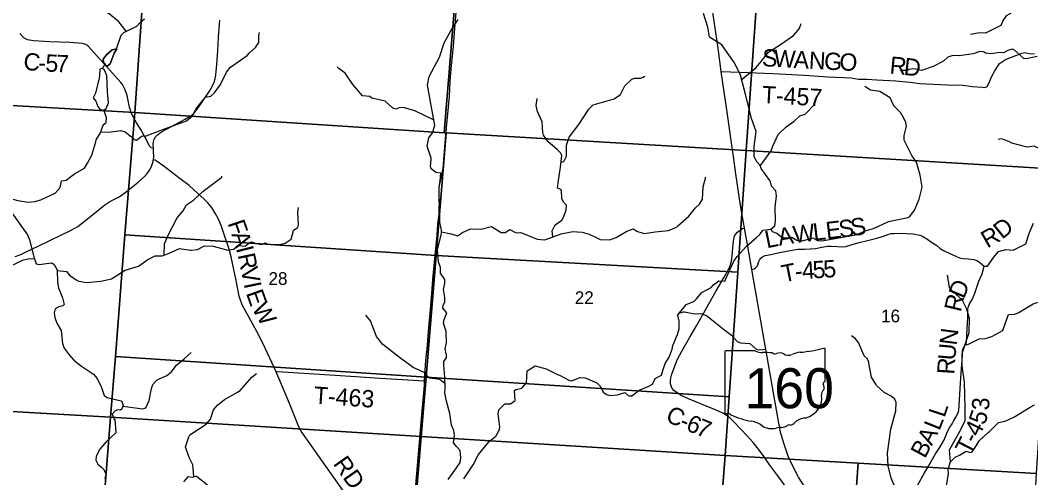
# Model space of a CAD drawing. Extents: x 1878108 to 2183446, y 146837 to 508383.
# Drawn here: x 2019382 to 2036927, y 325051 to 333002 of the extents above; entities that cross this region are included whole.
import ezdxf

# ---------------------------------------------------------------- set-up
doc = ezdxf.new("R2010")
doc.units = 0
for name, color, linetype in [('GM_X_County_Road', 7, 'Continuous'), ('GM_X_County_Road_Text', 7, 'Continuous'), ('GM_X_Minor_River', 7, 'Continuous'), ('GM_X_Section', 7, 'Continuous'), ('GM_X_Section_Text', 7, 'Continuous'), ('GM_X_State_Location', 7, 'Continuous'), ('GM_X_State_Route', 7, 'Continuous'), ('GM_X_State_Shield', 7, 'Continuous'), ('GM_X_Township_Road', 7, 'Continuous'), ('GM_X_Township_Road_Text', 7, 'Continuous')]:
    doc.layers.add(name, color=color, linetype=linetype)

msp = doc.modelspace()

# ---------------------------------------------------------------- linework, layer by layer
at = {"layer": 'GM_X_County_Road'}
for points in [[(2021694, 330779), (2021657, 330787), (2021633, 330810), (2021604, 330859), (2021557, 330956), (2021517, 331028), (2021476, 331101), (2021403, 331219), (2021342, 331322), (2021306, 331396), (2021281, 331490), (2021236, 331695), (2021204, 331794), (2021182, 331838), (2021158, 331884), (2021128, 331922), (2020833, 332251), (2020554, 332559), (2020521, 332581), (2020465, 332595), (2020246, 332612), (2019895, 332626), (2019611, 332642), (2019511, 332659), (2019444, 332693), (2019378, 332769)], [(2024994, 324816), (2024620, 325350), (2024257, 325861), (2024217, 325934), (2024056, 326341), (2023824, 326894), (2023598, 327379), (2023487, 327591), (2023235, 328056), (2023204, 328139), (2023185, 328209), (2023129, 328482), (2023067, 328783), (2023042, 328889), (2023008, 329025), (2022934, 329242), (2022869, 329436), (2022823, 329543), (2022770, 329640), (2022713, 329738), (2022640, 329828), (2022578, 329891), (2022397, 330057), (2022313, 330127), (2022157, 330244), (2021858, 330477), (2021757, 330549), (2021727, 330568), (2021697, 330574)], [(2032708, 324847), (2032533, 325086), (2032399, 325271), (2032285, 325431), (2032174, 325577), (2032105, 325666), (2032005, 325778), (2031886, 325902), (2031769, 326024), (2031704, 326091), (2031641, 326136), (2031578, 326173), (2031464, 326226), (2030982, 326424), (2030870, 326477), (2030789, 326525), (2030732, 326570), (2030703, 326603), (2030687, 326633), (2030674, 326681), (2030673, 326743), (2030679, 326785), (2030697, 326854), (2030734, 326960), (2030795, 327114), (2030867, 327250), (2031010, 327493), (2031123, 327693), (2031251, 327920), (2031339, 328076), (2031465, 328299), (2031602, 328535), (2031682, 328682), (2031714, 328754), (2031730, 328817), (2031744, 328906), (2031752, 329050), (2031763, 329161), (2031777, 329230), (2031795, 329270), (2031836, 329321), (2031869, 329350), (2031920, 329381), (2031956, 329391)]]:
    msp.add_lwpolyline(points, dxfattribs=at)
at = {"layer": 'GM_X_Minor_River'}
for points in [[(2037847, 334758), (2037838, 334558), (2037785, 334398), (2037647, 334207), (2037617, 334135), (2037617, 334051), (2037463, 333997), (2037366, 333946), (2037172, 333762), (2037056, 333721), (2036811, 333571), (2036785, 333549), (2036769, 333497), (2036763, 333471), (2036705, 333288), (2036561, 333110), (2036497, 333076), (2036446, 333003), (2036406, 332909), (2036222, 332817), (2036138, 332779), (2036036, 332780), (2035878, 332756)], [(2021222, 332809), (2021096, 332976), (2020928, 333114), (2020608, 333292), (2020441, 333362), (2020379, 333429), (2020312, 333560), (2020294, 333608)], [(2021056, 332503), (2021134, 332742), (2021182, 332790), (2021404, 332897), (2021464, 332963), (2021542, 333027)], [(2026450, 330845), (2026477, 330958), (2026542, 331044), (2026578, 331175), (2026536, 331429), (2026450, 331871), (2026481, 332023), (2026659, 332360), (2026744, 332609), (2026862, 332831), (2026984, 333012)], [(2031769, 328816), (2031827, 328899), (2031989, 329076), (2032164, 329224), (2032222, 329277), (2032276, 329355), (2032412, 329373), (2032482, 329427), (2032494, 329509), (2032489, 329752), (2032509, 329942), (2032503, 330036), (2032425, 330118), (2032409, 330196), (2032397, 330214), (2032243, 330428), (2032227, 330480), (2032175, 330534), (2032127, 330626), (2032125, 330806), (2032156, 331071), (2032080, 331295), (2031978, 331695), (2031889, 332046), (2031783, 332260), (2031653, 332440), (2031565, 332572), (2031351, 332706), (2031319, 332882), (2031243, 333120)], [(2031914, 331976), (2032161, 332180), (2032243, 332283), (2032373, 332447), (2032582, 332578), (2032808, 332734), (2032880, 332821), (2032913, 332865), (2032939, 332945)], [(2020782, 331060), (2020921, 331055), (2021126, 331086), (2021206, 331060), (2021378, 330922), (2021402, 330920), (2021446, 330950), (2021490, 330986), (2021568, 330991), (2021857, 331103), (2022267, 331254), (2022373, 331343), (2022430, 331457), (2022542, 331595), (2022600, 331665), (2022694, 331682), (2022754, 331738), (2022780, 331776), (2022855, 331876), (2022965, 332101), (2023035, 332187), (2023320, 332390), (2023358, 332432), (2023466, 332526), (2023524, 332614), (2023526, 332737), (2023534, 332791)], [(2021057, 332504), (2020977, 332487), (2020883, 332407), (2020823, 332325), (2020829, 332273), (2020859, 332243)], [(2020859, 332243), (2020829, 332273), (2020823, 332325), (2020883, 332407), (2020977, 332487), (2021057, 332504), (2021015, 332427), (2020941, 332243), (2020893, 332203), (2020875, 332211), (2020859, 332243)], [(2020859, 332243), (2020875, 332211), (2020893, 332203), (2020941, 332243), (2021015, 332427), (2021057, 332504)], [(2037038, 332372), (2036874, 332337), (2036814, 332329), (2036636, 332489), (2036602, 332497), (2036528, 332477), (2036454, 332435), (2036380, 332439), (2036244, 332416), (2036143, 332428), (2036117, 332446), (2036099, 332454), (2036043, 332456), (2035929, 332416), (2035681, 332383), (2035571, 332387), (2035485, 332359), (2035413, 332291), (2035232, 332196), (2035032, 332126), (2034896, 332155), (2034812, 332143), (2034788, 332127), (2034700, 332129)], [(2020834, 331438), (2020876, 331470), (2020912, 331564), (2020900, 331756), (2020888, 332043), (2020843, 332133), (2020809, 332165), (2020766, 332149), (2020756, 332042), (2020756, 332026), (2020690, 331736), (2020648, 331656), (2020692, 331596), (2020730, 331502), (2020762, 331456), (2020834, 331438)], [(2020766, 332149), (2020756, 332042), (2020756, 332026), (2020690, 331736), (2020648, 331656), (2020692, 331596), (2020730, 331502), (2020762, 331456), (2020834, 331438)], [(2020834, 331438), (2020876, 331470), (2020912, 331564), (2020900, 331756), (2020888, 332043), (2020843, 332133), (2020809, 332165), (2020766, 332149)], [(2020809, 332165), (2020859, 332243)], [(2026556, 331269), (2026234, 331426), (2026036, 331488), (2025953, 331480), (2025913, 331454), (2025851, 331476), (2025715, 331597), (2025489, 331649), (2025449, 331675), (2025323, 331687), (2025157, 331887), (2025021, 332083), (2024913, 332165), (2024887, 332191)], [(2028777, 330536), (2028818, 330548), (2028868, 330638), (2028866, 330828), (2028914, 330971), (2029079, 331191), (2029255, 331456), (2029331, 331532), (2029694, 331637), (2029802, 331709), (2029880, 331864), (2029998, 331978), (2030053, 331994), (2030155, 331994), (2030199, 332014), (2030225, 332027)], [(2032412, 329373), (2032434, 329329), (2032518, 329299), (2032590, 329245), (2032648, 329223), (2032780, 329232), (2032864, 329178), (2032964, 329168), (2033141, 329218), (2033221, 329172), (2033301, 329166), (2033695, 329237), (2033912, 329276), (2034036, 329338), (2034198, 329382), (2034442, 329501), (2034458, 329505), (2034791, 329574), (2034827, 329594), (2034905, 329700), (2034989, 329893), (2035042, 330099), (2035006, 330309), (2034940, 330535), (2034860, 330653), (2034730, 330917), (2034726, 330998), (2034767, 331162), (2034757, 331222), (2034699, 331348), (2034681, 331364), (2034671, 331392), (2034551, 331516), (2034485, 331654), (2034307, 331762), (2034145, 331788), (2034047, 331853)], [(2028626, 329237), (2028620, 329344), (2028668, 329444), (2028784, 329529), (2028812, 329581), (2028863, 329701), (2028867, 329791), (2028813, 329839), (2028783, 329903), (2028777, 330043), (2028769, 330059), (2028707, 330081), (2028723, 330177), (2028763, 330450), (2028784, 330654), (2028764, 330700), (2028724, 330738), (2028704, 330758), (2028550, 330886), (2028464, 331004), (2028456, 331052), (2028444, 331236), (2028362, 331416), (2028342, 331518), (2028356, 331643)], [(2032237, 330476), (2032418, 330735), (2032442, 330799), (2032538, 331018), (2032678, 331148), (2032817, 331248), (2032915, 331343), (2033007, 331371), (2033039, 331397), (2033149, 331515), (2033203, 331612)], [(2019049, 329960), (2019144, 329967), (2019252, 329895), (2019342, 329867), (2019522, 329841), (2019633, 329849), (2019739, 329880), (2019987, 329998), (2020077, 330093), (2020100, 330209), (2020182, 330225), (2020324, 330333), (2020500, 330432), (2020548, 330520), (2020627, 330656), (2020693, 330887), (2020703, 330921), (2020777, 331043), (2020817, 331169), (2020841, 331197), (2020872, 331224), (2020882, 331310), (2020834, 331438)], [(2037564, 330869), (2037516, 330867), (2037495, 330816), (2037375, 330760), (2037217, 330772), (2037097, 330764), (2036983, 330811), (2036865, 330797), (2036595, 330863), (2036545, 330897), (2036420, 330943), (2036360, 330930)], [(2026811, 325022), (2026955, 325223), (2027019, 325319), (2027031, 325398), (2027019, 325524), (2026953, 325602), (2026937, 325616), (2026907, 325658), (2026921, 325781), (2026909, 325875), (2026872, 325967), (2026842, 326168), (2026784, 326384), (2026756, 326527), (2026758, 326609), (2026752, 326799), (2026736, 327008), (2026736, 327074), (2026783, 327138), (2026781, 327193), (2026779, 327205), (2026759, 327299), (2026781, 327391), (2026779, 327594), (2026731, 327736), (2026743, 327804), (2026787, 327919), (2026719, 327997), (2026723, 328045), (2026753, 328109), (2026751, 328186), (2026732, 328320), (2026752, 328426), (2026752, 328498), (2026676, 328605), (2026676, 328619), (2026678, 328703), (2026644, 328805), (2026628, 329018), (2026694, 329291), (2026696, 329361), (2026665, 329485), (2026659, 329738), (2026655, 329935), (2026653, 330091), (2026673, 330209), (2026685, 330342), (2026599, 330358), (2026561, 330384), (2026519, 330422), (2026505, 330458), (2026515, 330590), (2026515, 330604), (2026448, 330815), (2026450, 330845)], [(2021881, 328921), (2021888, 329119), (2021955, 329277), (2022105, 329570), (2022211, 329692), (2022267, 329796), (2022388, 329875), (2022556, 330029), (2022883, 330276), (2022881, 330290)], [(2026694, 329322), (2026866, 329291), (2026976, 329253), (2027060, 329311), (2027200, 329377), (2027387, 329374), (2027565, 329416), (2027729, 329316), (2027801, 329314), (2027885, 329363), (2027979, 329313), (2028037, 329307), (2028075, 329311), (2028358, 329195), (2028482, 329184), (2028506, 329194), (2028774, 329290), (2028974, 329333), (2029139, 329317), (2029257, 329285), (2029359, 329237), (2029449, 329189), (2029621, 329188), (2029731, 329224), (2029911, 329338), (2030022, 329375), (2030098, 329329), (2030222, 329297), (2030406, 329327), (2030638, 329350), (2030776, 329408), (2030800, 329428), (2030987, 329599), (2031105, 329741), (2031177, 329803), (2031227, 329890), (2031238, 330106), (2031286, 330280)], [(2020022, 328653), (2020188, 328635), (2020238, 328573), (2020354, 328491), (2020402, 328465), (2020534, 328445), (2020784, 328466), (2020965, 328510), (2021203, 328657), (2021435, 328731), (2021596, 328844), (2021724, 328906), (2021848, 328908), (2021956, 328951), (2022146, 329033), (2022331, 329005), (2022347, 329005), (2022459, 329016), (2022583, 329080), (2022729, 329076), (2022989, 329009), (2023086, 329025), (2023138, 329063), (2023176, 329087), (2023288, 329073), (2023374, 329144), (2023404, 329152), (2023444, 329134), (2023564, 329106), (2023642, 329136), (2023668, 329112), (2023859, 329105), (2023883, 329105), (2023983, 329127), (2024085, 329199), (2024121, 329325), (2024129, 329351), (2024203, 329402), (2024215, 329448), (2024204, 329662), (2024214, 329748)], [(2019239, 329657), (2019391, 329434), (2019403, 329418), (2019511, 329270), (2019543, 329184), (2019621, 328889), (2019661, 328771), (2019719, 328757), (2019791, 328767), (2019929, 328785), (2019971, 328759), (2020001, 328705), (2020021, 328663), (2020031, 328445), (2020044, 328352), (2020114, 328180), (2020144, 328064), (2020122, 328038), (2020050, 328021), (2020038, 328017), (2019990, 327989), (2019972, 327915), (2019984, 327837), (2020018, 327738), (2020094, 327612), (2020116, 327386), (2020142, 327305), (2020234, 327187)], [(2019634, 328847), (2019543, 328856), (2019417, 328828), (2019263, 328751), (2019155, 328721), (2018948, 328656), (2018784, 328652), (2018614, 328618), (2018470, 328587), (2018271, 328467), (2018041, 328432), (2017603, 328400), (2017451, 328383), (2017242, 328389), (2017112, 328357), (2017090, 328351), (2016956, 328286), (2016810, 328162), (2016727, 328112), (2016475, 327895)], [(2030822, 327909), (2030913, 328024), (2030945, 328063), (2031077, 328113), (2031121, 328161), (2031214, 328273), (2031376, 328360), (2031420, 328404), (2031508, 328472), (2031616, 328470), (2031676, 328615), (2031769, 328817)], [(2035535, 325327), (2035515, 325537), (2035679, 325826), (2035790, 326043), (2035790, 326269), (2035777, 326710), (2035735, 326988), (2035733, 327210), (2035854, 327573), (2035862, 327821), (2035814, 327981), (2035738, 328141), (2035574, 328287), (2035514, 328357), (2035478, 328572)], [(2035480, 328558), (2035480, 328557)], [(2035782, 327357), (2035847, 327375), (2036030, 327465), (2036138, 327471), (2036228, 327501), (2036248, 327508), (2036440, 327612), (2036488, 327744), (2036541, 327891), (2036645, 327893), (2036709, 327917), (2036967, 328072), (2037112, 328122), (2037212, 328162)], [(2027085, 325033), (2027246, 325278), (2027340, 325456), (2027525, 325681), (2027637, 325777), (2027687, 325855), (2027695, 325872), (2027711, 325928), (2027681, 326162), (2027691, 326232), (2027796, 326334), (2027894, 326335), (2027972, 326393), (2027962, 326565), (2027992, 326587), (2028092, 326607), (2028171, 326702), (2028181, 326912), (2028323, 326996), (2028511, 326943), (2028709, 326847), (2028745, 326837), (2028917, 326739), (2028953, 326737), (2029046, 326769), (2029098, 326793), (2029190, 326786), (2029390, 326700), (2029460, 326632), (2029504, 326540), (2029562, 326498), (2029618, 326482), (2029750, 326494), (2029878, 326532), (2029938, 326479), (2029952, 326473), (2029998, 326475), (2030130, 326573), (2030293, 326645), (2030359, 326680), (2030407, 326776), (2030515, 326834), (2030537, 326914), (2030579, 327036), (2030646, 327149), (2030700, 327287), (2030710, 327351), (2030796, 327540), (2030820, 327638), (2030821, 327774), (2030799, 327876), (2030823, 327910), (2030893, 327932), (2030915, 327932), (2031091, 327901), (2031197, 327903), (2031297, 327869), (2031613, 327615), (2031733, 327531), (2031827, 327421), (2031885, 327397), (2032047, 327382), (2032159, 327288), (2032209, 327276), (2032328, 327288)], [(2026755, 326692), (2026665, 326757), (2026487, 326782), (2026393, 326882), (2026205, 326970), (2025969, 327142), (2025677, 327366), (2025567, 327504), (2025461, 327778), (2025380, 327875)], [(2034682, 324765), (2034550, 324933), (2034502, 325043), (2034450, 325259), (2034440, 325477), (2034495, 325898), (2034583, 326217), (2034592, 326359), (2034564, 326419), (2034500, 326467), (2034382, 326535), (2034248, 326655), (2034224, 326695), (2034160, 326797), (2034114, 327045), (2034114, 327059), (2034086, 327123), (2034036, 327171), (2033936, 327399), (2033882, 327467), (2033812, 327517), (2033812, 327516)], [(2021162, 326297), (2021509, 326250), (2021563, 326264), (2021621, 326392), (2021659, 326601), (2021683, 326673), (2021761, 326755), (2021930, 326826), (2022004, 326884), (2022094, 327008), (2022230, 327117), (2022347, 327227)], [(2020234, 327187), (2020314, 327097), (2020445, 326989), (2020653, 326853), (2020719, 326779), (2020787, 326634), (2020791, 326622), (2020841, 326482), (2020889, 326446), (2021135, 326388), (2021147, 326370), (2021167, 326312), (2021145, 326246), (2021117, 326228), (2021073, 326232), (2021023, 326210), (2020981, 326157), (2021007, 326079), (2021013, 326065), (2021025, 326071), (2021043, 325842), (2021043, 325832), (2020871, 325670), (2020766, 325551), (2020698, 325427), (2020692, 325360), (2020732, 325288), (2020794, 325234), (2020832, 325196), (2020868, 325118), (2020852, 325040)], [(2022396, 325071), (2022378, 325274), (2022313, 325405), (2022253, 325591), (2022309, 325765), (2022329, 325799), (2022608, 325982), (2022684, 326068), (2022736, 326230), (2022806, 326311), (2022928, 326409), (2023153, 326540), (2023203, 326570), (2023401, 326801), (2023482, 326865)], [(2035775, 326704), (2035776, 326705)], [(2035460, 324884), (2035498, 325119), (2035493, 325199), (2035535, 325327), (2035613, 325409), (2035689, 325446), (2035803, 325514), (2035875, 325492), (2035907, 325504), (2035959, 325580), (2036030, 325695), (2036190, 325841), (2036208, 325853), (2036368, 326014), (2036480, 326034), (2036631, 326104), (2036915, 326277), (2036993, 326319)], [(2022223, 324980), (2022303, 325076), (2022369, 325064), (2022431, 325079), (2022443, 325079), (2022631, 324927)]]:
    msp.add_lwpolyline(points, dxfattribs=at)
at = {"layer": 'GM_X_Section'}
for points in [[(2021742, 336707), (2021373, 331397), (2015959, 331706), (2015982, 331960), (2016318, 337016)], [(2027176, 336347), (2026745, 331046), (2021373, 331397), (2021742, 336707)], [(2032358, 336020), (2031987, 330736), (2026777, 331044), (2026745, 331046), (2027176, 336347)], [(2037721, 335715), (2037378, 330411), (2031987, 330736), (2032358, 336020)], [(2015959, 331706), (2021373, 331397), (2021200, 329271), (2021036, 327160), (2020952, 326107), (2015592, 326412), (2015609, 326604)], [(2021373, 331397), (2026745, 331046), (2026777, 331044), (2026602, 328916), (2021200, 329271)], [(2026777, 331044), (2031987, 330736), (2031841, 328623), (2026602, 328916)], [(2031987, 330736), (2037378, 330411), (2037233, 328304), (2037084, 326108), (2037018, 325126), (2033930, 325304), (2031621, 325441), (2031691, 326457), (2031841, 328623)], [(2021200, 329271), (2026602, 328916), (2026429, 326802), (2021036, 327160)], [(2026602, 328916), (2031841, 328623), (2031691, 326457), (2026429, 326802)], [(2026429, 326802), (2026345, 325770), (2020952, 326107), (2021036, 327160)], [(2031691, 326457), (2031621, 325441), (2026345, 325770), (2026429, 326802)], [(2020952, 326107), (2020858, 324918), (2020535, 320785), (2015233, 321110), (2015243, 321224), (2015592, 326412)], [(2020952, 326107), (2026345, 325770), (2026247, 324581), (2023639, 324740), (2020858, 324918)], [(2026345, 325770), (2031621, 325441), (2031529, 324243), (2030528, 324309), (2026522, 324560), (2026247, 324581)], [(2033930, 325304), (2033640, 321275), (2031322, 321425), (2031529, 324243), (2031621, 325441)], [(2036950, 323886), (2036627, 323893), (2036447, 321096), (2033640, 321275), (2033930, 325304), (2037018, 325126)]]:
    msp.add_lwpolyline(points, close=True, dxfattribs=at)
at = {"layer": 'GM_X_State_Route'}
for points in [[(2031736, 330830), (2031654, 331404), (2031554, 332111), (2031497, 332517), (2031435, 332946), (2031368, 333413)], [(2019296, 328895), (2019390, 328931), (2019473, 328971), (2019707, 329084), (2020087, 329267), (2020245, 329341), (2020319, 329382), (2020382, 329420), (2020608, 329595), (2020851, 329794), (2020922, 329843), (2020993, 329880), (2021076, 329921), (2021136, 329959), (2021206, 330009), (2021281, 330067), (2021343, 330120), (2021431, 330186), (2021537, 330289), (2021583, 330337), (2021625, 330395), (2021655, 330451), (2021680, 330515), (2021697, 330574), (2021702, 330636), (2021698, 330716), (2021694, 330779), (2021688, 330847), (2021695, 330891), (2021707, 330933), (2021730, 330973), (2021764, 331011), (2021795, 331035), (2021837, 331064), (2022243, 331283), (2022346, 331340), (2022394, 331379), (2022427, 331419), (2022472, 331480), (2022533, 331571), (2022667, 331769), (2022715, 331853), (2022747, 331926), (2022767, 331985), (2022776, 332048), (2022784, 332117), (2022795, 332225), (2022812, 332475), (2022827, 332710), (2022841, 332927), (2022850, 333005)], [(2026923, 332785), (2026928, 332865), (2026951, 333135), (2026953, 333154)], [(2026737, 330573), (2026738, 330580), (2026770, 331011), (2026832, 331676), (2026848, 331944), (2026865, 332156), (2026881, 332327), (2026906, 332553), (2026923, 332785)], [(2033022, 324866), (2032896, 325063), (2032790, 325264), (2032717, 325428), (2032649, 325619), (2032588, 325821), (2032550, 326003), (2032499, 326294), (2032130, 328405), (2032085, 328670), (2032008, 329103), (2031956, 329391), (2031888, 329780), (2031807, 330333), (2031764, 330633), (2031736, 330830)], [(2026658, 330105), (2026665, 330152), (2026694, 330292), (2026725, 330426), (2026737, 330573)], [(2026220, 324584), (2026358, 326217), (2026399, 326656), (2026402, 326734), (2026425, 327088), (2026451, 327351), (2026466, 327529), (2026510, 328040), (2026532, 328327), (2026546, 328498), (2026575, 328800), (2026620, 329268), (2026634, 329456), (2026653, 329634), (2026658, 329728), (2026662, 329833), (2026653, 329960), (2026653, 330067), (2026658, 330105)]]:
    msp.add_lwpolyline(points, dxfattribs=at)
at = {"layer": 'GM_X_State_Shield'}
for p, q in [((2031615, 327241), (2031615, 326184)), ((2032142, 327259), (2031632, 327259)), ((2033355, 326733), (2033355, 327285)), ((2033355, 326733), (2033355, 326733))]:
    msp.add_line(p, q, dxfattribs=at)
for centre, major_axis, start_param, end_param in [((2031635, 327243), (20.2, 0), 1.712693, 3.28349), ((2032263, 327382), (196, 0), 4.042523, 4.731795), ((2032328, 326666), (702, 0), 1.404758, 1.657858), ((2032487, 327249), (56.4, 0), 3.836095, 5.185415), ((2032570, 327127), (117, 0), 0.950623, 2.079405), ((2032971, 326937), (371, 0), 1.699011, 2.107814), ((2032735, 328700), (1845, 0), 4.814394, 5.042369), ((2033336, 327288), (19.4, 0), 6.141152, 7.989035), ((2032721, 327294), (141, 0), 4.081561, 5.145723), ((2033351, 326692), (30, 0), 1.883978, 3.671073), ((2033334, 326731), (20.7, 0), 5.05454, 6.418171), ((2033424, 326501), (131, 0), 2.387724, 3.262537), ((2033160, 326622), (180, 0), 5.934695, 6.695948), ((2032839, 326431), (462, 0), 5.101752, 6.440018), ((2031635, 326182), (20.3, 0), 3.00124, 4.508301), ((2031638, 326290), (155, 0), 4.665946, 4.897461), ((2031670, 326124), (56, 0), 0.519207, 1.627899), ((2032376, 327073), (1333, 0), 4.195997, 4.488961), ((2031979, 325710), (417, 0), 0.823519, 1.323587), ((2032713, 326082), (149, 0), 4.937069, 5.64225), ((2033033, 325888), (253, 0), 1.647645, 2.488434), ((2032430, 326118), (265, 0), 4.026481, 4.996735), ((2032583, 325753), (217, 0), 1.495662, 1.94098), ((2032602, 326039), (141, 0), 4.691044, 5.507374), ((2032730, 325937), (39.7, 0), 1.147584, 2.315152)]:
    msp.add_ellipse(centre, major_axis=major_axis, ratio=0.8, start_param=start_param, end_param=end_param, dxfattribs=at)
at = {"layer": 'GM_X_Township_Road'}
for points in [[(2031554, 332111), (2031878, 332099), (2032447, 332075), (2033000, 332047), (2033401, 332018), (2033808, 332002), (2033936, 331978), (2034088, 331979), (2034252, 331966), (2034582, 331947), (2034834, 331923), (2034996, 331900), (2035481, 331879), (2035753, 331871), (2035909, 331853), (2036091, 331839), (2036129, 331835), (2036168, 331852), (2036197, 331905), (2036247, 332018), (2036306, 332134), (2036382, 332248), (2036488, 332317), (2036770, 332427), (2036826, 332438), (2036897, 332425), (2036993, 332416)], [(2036115, 328727), (2036173, 328726), (2036284, 328885), (2036364, 328982), (2036496, 329016), (2036622, 329004), (2036838, 329115), (2036905, 329316), (2036971, 329478)], [(2032085, 328670), (2032123, 328681), (2032153, 328703), (2032181, 328735), (2032207, 328809), (2032225, 328846), (2032246, 328873), (2032277, 328894), (2032313, 328911), (2032414, 328932), (2032563, 328963), (2032751, 329002), (2032890, 329021), (2032998, 329025), (2033098, 329031), (2033187, 329038), (2033297, 329059), (2033398, 329075), (2033461, 329077), (2033570, 329069), (2033652, 329062), (2033715, 329068), (2033841, 329108), (2033945, 329142), (2034092, 329175), (2034253, 329217), (2034368, 329252), (2034460, 329285), (2034502, 329293), (2034556, 329298), (2034658, 329304), (2034878, 329289), (2034999, 329269), (2035048, 329247), (2035120, 329204), (2035203, 329145), (2035294, 329085), (2035354, 329035), (2035413, 328999), (2035523, 328947), (2035638, 328894), (2035688, 328875), (2035755, 328863), (2035841, 328854), (2035940, 328845), (2035992, 328829), (2036037, 328799), (2036115, 328727)], [(2035132, 325225), (2035156, 325264), (2035227, 325384), (2035275, 325465), (2035354, 325590), (2035418, 325697), (2035449, 325780), (2035480, 325855), (2035524, 325931), (2035560, 325991), (2035583, 326035), (2035624, 326107), (2035658, 326168), (2035676, 326223), (2035682, 326305), (2035696, 326507), (2035714, 326790), (2035722, 326949), (2035736, 327086), (2035740, 327195), (2035741, 327254), (2035749, 327286), (2035770, 327326), (2035799, 327371), (2035808, 327416), (2035815, 327532), (2035822, 327640), (2035835, 327828), (2035836, 327980), (2035844, 328026), (2035856, 328065), (2035910, 328151), (2035950, 328241), (2035999, 328400), (2036025, 328465), (2036081, 328595), (2036100, 328656), (2036102, 328666), (2036115, 328727)], [(2023824, 326894), (2023851, 326897), (2024032, 326889), (2024850, 326833), (2025289, 326803), (2025539, 326789), (2026402, 326734)], [(2034654, 324353), (2034722, 324482), (2034854, 324727), (2034958, 324915), (2035079, 325140), (2035132, 325225)]]:
    msp.add_lwpolyline(points, dxfattribs=at)

# ---------------------------------------------------------------- texts
at = {"layer": 'GM_X_County_Road_Text'}
for s, rotation, p in [('C', 354.1865, (2019427, 332144)), ('5', 357.4387, (2019814, 332111)), ('7', 357.5886, (2019999, 332103)), ('-', 357.0158, (2019688, 332117)), ('F', 288.7896, (2022980, 329475)), ('A', 288.2748, (2023045, 329284)), ('I', 284.4301, (2023126, 329039)), ('R', 282.0272, (2023156, 328923)), ('V', 281.735, (2023207, 328682)), ('I', 281.8287, (2023261, 328423)), ('E', 289.6214, (2023298, 328260)), ('W', 299.418, (2023397, 327997)), ('C', 333.1609, (2030566, 326052)), ('-', 337.6923, (2030810, 325930)), ('6', 337.7491, (2030924, 325883)), ('7', 337.3317, (2031095, 325814)), ('RD', 305.1937, (2024804, 325294))]:
    msp.add_text(s, height=300, rotation=rotation, dxfattribs=at).set_placement(p)
at = {"layer": 'GM_X_Section_Text'}
for s, p in [('28', (2023693, 328403)), ('22', (2029010, 328071)), ('16', (2034328, 327752))]:
    msp.add_text(s, height=221, rotation=0, dxfattribs=at).set_placement(p)
at = {"layer": 'GM_X_State_Location'}
msp.add_text('160', height=1, rotation=0, dxfattribs=at).set_placement((2032112, 326570))
for s in ['s', 'r']:
    msp.add_text(s, height=1, dxfattribs=at).set_placement((2032465, 326643))
at = {"layer": 'GM_X_State_Shield'}
msp.add_text('160', height=696.1, dxfattribs=at).set_placement((2031956, 326259))
at = {"layer": 'GM_X_Township_Road_Text'}
for s, rotation, p in [('S', 356.929, (2032255, 332204)), ('W', 356.9276, (2032457, 332193)), ('A', 356.9277, (2032804, 332174)), ('N', 356.9277, (2033068, 332160)), ('G', 356.9338, (2033332, 332146)), ('O', 357.5587, (2033599, 332132)), ('R', 354.6335, (2034468, 332076)), ('D', 353.6377, (2034712, 332053)), ('T-457', 356.9129, (2032252, 331562)), ('E', 6.7135, (2033385, 329195)), ('S', 6.8068, (2033608, 329221)), ('S', 9.0968, (2033822, 329247)), ('D', 39.2532, (2036430, 329185)), ('L', 11.5159, (2032343, 329038)), ('A', 9.6629, (2032561, 329082)), ('W', 7.0783, (2032817, 329126)), ('L', 6.7136, (2033162, 329169)), ('R', 29.7696, (2036172, 329033)), ('4', 3.9269, (2032965, 328501)), ('5', 3.713, (2033149, 328514)), ('5', 3.6922, (2033334, 328526)), ('T', 11.4763, (2032633, 328445)), ('-', 6.2497, (2032846, 328488)), ('D', 67.24, (2035764, 328148)), ('R', 76.5686, (2035711, 327920)), ('N', 82.772, (2035637, 327343)), ('U', 84.8313, (2035614, 327083)), ('R', 86.3131, (2035598, 326840)), ('T-463', 356.0726, (2024473, 326340)), ('3', 87.4669, (2036201, 326218)), ('L', 71.6506, (2035430, 326086)), ('5', 71.7919, (2036127, 325955)), ('L', 67.9859, (2035339, 325858)), ('4', 63.5562, (2036027, 325746)), ('A', 62.9359, (2035207, 325597)), ('B', 61.9512, (2035088, 325374)), ('T', 62.8446, (2035867, 325433)), ('-', 62.969, (2035970, 325633))]:
    msp.add_text(s, height=300, rotation=rotation, dxfattribs=at).set_placement(p)

doc.saveas('drawing.dxf')
